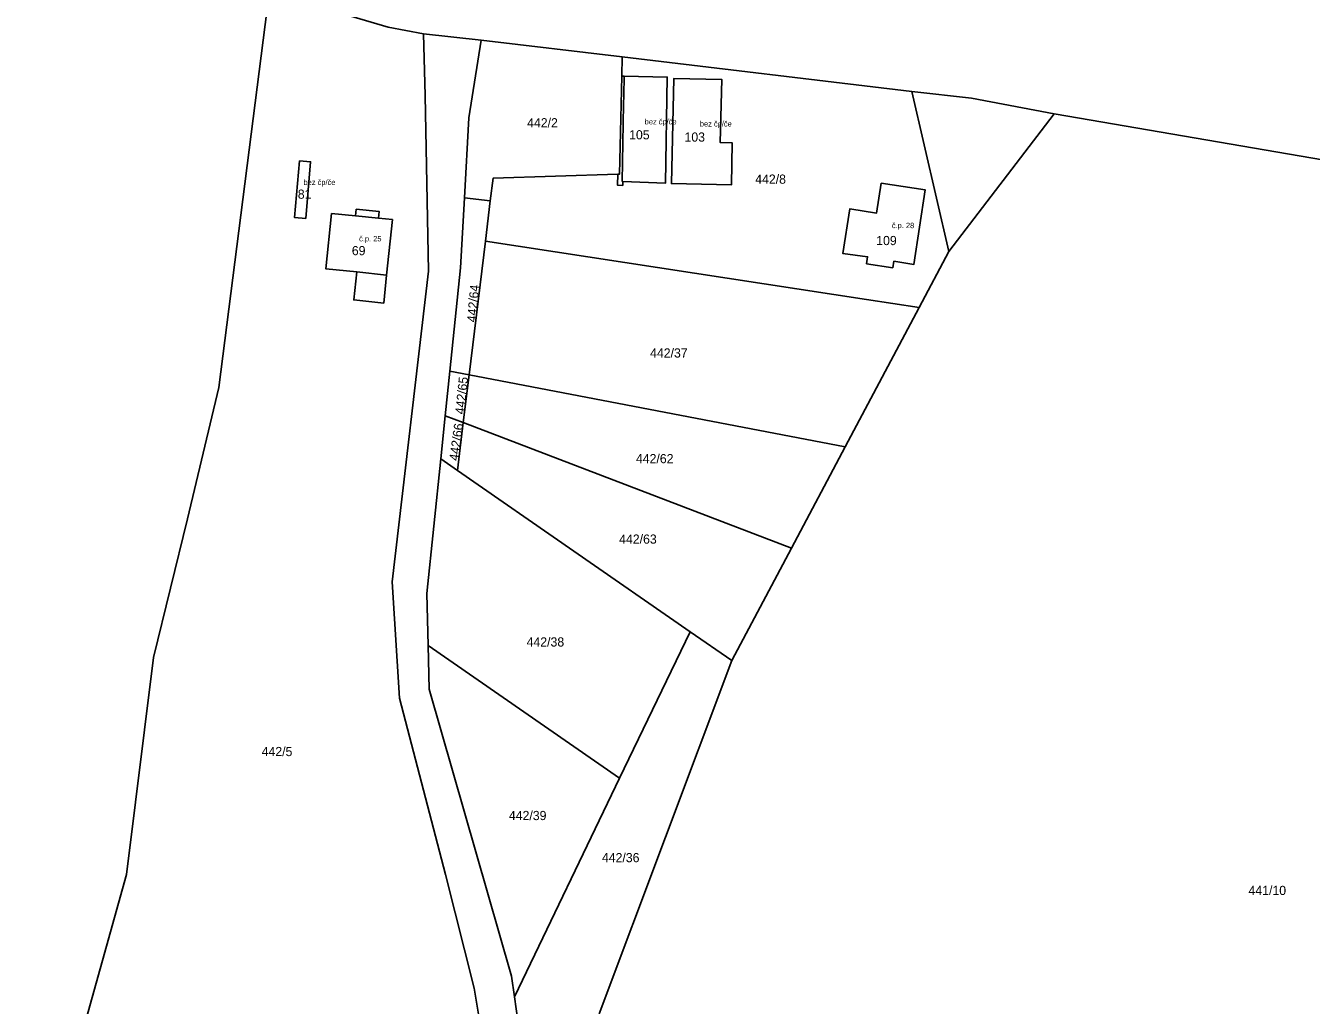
# Model space of a CAD drawing. Extents: x -880531 to -877616, y -1023932 to -1021350.
# Drawn here: x -880275.5 to -880037.5, y -1022775.2 to -1022593.9 of the extents above; entities that cross this region are included whole.
import ezdxf

# ---------------------------------------------------------------- set-up
doc = ezdxf.new("R2010")
doc.units = 0
for name, color, linetype in [('Definiční body', 7, 'Continuous'), ('Hranice parcel', 7, 'Continuous'), ('Parcelní čísla', 7, 'Continuous'), ('Polygon budovy', 7, 'Continuous'), ('Vnitřní kresba', 7, 'Continuous')]:
    doc.layers.add(name, color=color, linetype=linetype)

msp = doc.modelspace()

# ---------------------------------------------------------------- linework, layer by layer
at = {"layer": 'Hranice parcel'}
for p, q in [((-880191.14, -1022596.56), (-880201.85, -1022595.42)), ((-880165.02, -1022599.62), (-880191.14, -1022596.56)), ((-880165.11, -1022603.24), (-880165.02, -1022599.62)), ((-880165.11, -1022603.24), (-880164.68, -1022603.25)), ((-880194.24, -1022625.73), (-880189.45, -1022626.3)), ((-880189.45, -1022626.3), (-880190.36, -1022633.76)), ((-880190.36, -1022633.76), (-880193.39, -1022658.51)), ((-880123.76, -1022671.82), (-880110.08, -1022646.06)), ((-880196.94, -1022657.83), (-880197.79, -1022666.07)), ((-880193.39, -1022658.51), (-880196.94, -1022657.83)), ((-880193.39, -1022658.51), (-880194.47, -1022667.34)), ((-880193.39, -1022658.51), (-880123.76, -1022671.82)), ((-880198.62, -1022674.04), (-880197.79, -1022666.07)), ((-880197.79, -1022666.07), (-880194.47, -1022667.34)), ((-880194.47, -1022667.34), (-880195.55, -1022676.17)), ((-880194.47, -1022667.34), (-880133.71, -1022690.56)), ((-880133.71, -1022690.56), (-880123.76, -1022671.82)), ((-880195.55, -1022676.17), (-880198.62, -1022674.04)), ((-880152.45, -1022706.02), (-880195.55, -1022676.17)), ((-880133.71, -1022690.56), (-880144.75, -1022711.36)), ((-880152.45, -1022706.02), (-880165.51, -1022733.13)), ((-880144.75, -1022711.36), (-880152.45, -1022706.02)), ((-880200.98, -1022708.57), (-880165.51, -1022733.13)), ((-880169.29, -1022776.73), (-880144.75, -1022711.36)), ((-880165.51, -1022733.13), (-880184.98, -1022773.58))]:
    msp.add_line(p, q, dxfattribs=at)
for points in [[(-880201.85, -1022595.42), (-880208.37, -1022594.15), (-880224.11, -1022589.52), (-880229.6, -1022581.58)], [(-880275.46, -1022817.7), (-880256.82, -1022750.96), (-880251.78, -1022710.78), (-880245.5, -1022685.14), (-880239.72, -1022660.82), (-880229.65, -1022581.98)], [(-880201.85, -1022595.42), (-880201.5, -1022606.82), (-880200.91, -1022639.32), (-880207.63, -1022696.81), (-880206.25, -1022718.31), (-880197.77, -1022750.95), (-880192.42, -1022771.99), (-880190.9, -1022781.26)], [(-880191.14, -1022596.56), (-880193.43, -1022610.91), (-880194.24, -1022625.73)], [(-880085.09, -1022610.19), (-880100.38, -1022607.29), (-880111.43, -1022606.07), (-880165.02, -1022599.62)], [(-880165.85, -1022621.37), (-880165.55, -1022621.36), (-880165.11, -1022603.24)], [(-880164.68, -1022603.25), (-880156.7, -1022603.38), (-880157.02, -1022623.01), (-880164.89, -1022622.7)], [(-880146.89, -1022615.53), (-880146.62, -1022603.84), (-880155.47, -1022603.64), (-880155.91, -1022623.1), (-880144.81, -1022623.36), (-880144.66, -1022615.58), (-880146.89, -1022615.53)], [(-880110.08, -1022646.06), (-880104.57, -1022635.67), (-880085.09, -1022610.19)], [(-880085.09, -1022610.19), (-880006.95, -1022623.58), (-879948.33, -1022639.86), (-879895.51, -1022661.38), (-879854.76, -1022684.53)], [(-880223.61, -1022629.54), (-880222.73, -1022619.05), (-880224.76, -1022618.92), (-880225.68, -1022629.39), (-880223.61, -1022629.54)], [(-880189.45, -1022626.3), (-880188.93, -1022622.11), (-880165.85, -1022621.37)], [(-880164.89, -1022622.7), (-880164.92, -1022623.44), (-880165.89, -1022623.4), (-880165.85, -1022621.37)], [(-880117.08, -1022623.02), (-880117.95, -1022628.55), (-880122.9, -1022627.78), (-880124.2, -1022636.02), (-880119.61, -1022636.65), (-880119.79, -1022637.93), (-880114.95, -1022638.69), (-880114.75, -1022637.47), (-880111.03, -1022638.06), (-880108.92, -1022624.26), (-880117.08, -1022623.02)], [(-880196.94, -1022657.83), (-880194.95, -1022638.71), (-880194.24, -1022625.73)], [(-880218.86, -1022628.64), (-880219.91, -1022638.86), (-880214.19, -1022639.45), (-880214.73, -1022644.64), (-880209.18, -1022645.22), (-880208.64, -1022640.02), (-880207.57, -1022629.75), (-880210.12, -1022629.5), (-880210, -1022628.28), (-880214.26, -1022627.86), (-880214.38, -1022629.08), (-880218.86, -1022628.64)], [(-880110.08, -1022646.06), (-880119.83, -1022644.57), (-880190.36, -1022633.76)], [(-880200.98, -1022708.57), (-880201.21, -1022698.97), (-880198.62, -1022674.04)], [(-880184.98, -1022773.58), (-880185.52, -1022769.75), (-880200.78, -1022716.69), (-880200.98, -1022708.57)], [(-880183.96, -1022798.18), (-880184.04, -1022780.28), (-880184.98, -1022773.58)]]:
    msp.add_lwpolyline(points, dxfattribs=at)
at = {"layer": 'Polygon budovy'}
for points in [[(-880164.68, -1022603.25), (-880164.73, -1022606.78), (-880164.82, -1022608.39), (-880165.02, -1022622.7), (-880164.89, -1022622.7), (-880157.02, -1022623.01), (-880156.7, -1022603.38)], [(-880146.62, -1022603.84), (-880155.47, -1022603.64), (-880155.91, -1022623.1), (-880144.81, -1022623.36), (-880144.66, -1022615.58), (-880146.89, -1022615.53)], [(-880225.68, -1022629.39), (-880223.61, -1022629.54), (-880222.73, -1022619.05), (-880224.76, -1022618.92)], [(-880117.08, -1022623.02), (-880117.95, -1022628.55), (-880122.9, -1022627.78), (-880124.2, -1022636.02), (-880119.61, -1022636.65), (-880119.79, -1022637.93), (-880114.95, -1022638.69), (-880114.75, -1022637.47), (-880111.03, -1022638.06), (-880108.92, -1022624.26)], [(-880218.86, -1022628.64), (-880219.91, -1022638.86), (-880214.19, -1022639.45), (-880208.64, -1022640.02), (-880207.57, -1022629.75), (-880210.12, -1022629.5), (-880214.38, -1022629.08)]]:
    msp.add_lwpolyline(points, close=True, dxfattribs=at)
at = {"layer": 'Vnitřní kresba'}
for p, q in [((-880164.68, -1022603.25), (-880164.73, -1022606.78)), ((-880164.73, -1022606.78), (-880164.82, -1022608.39)), ((-880111.43, -1022606.07), (-880104.57, -1022635.67)), ((-880164.82, -1022608.39), (-880165.02, -1022622.7)), ((-880165.02, -1022622.7), (-880164.89, -1022622.7)), ((-880214.38, -1022629.08), (-880210.12, -1022629.5)), ((-880214.19, -1022639.45), (-880208.64, -1022640.02))]:
    msp.add_line(p, q, dxfattribs=at)

# ---------------------------------------------------------------- texts
at = {"layer": 'Definiční body'}
for s, p in [('bez čp/če', (-880160.88, -1022612.15)), ('bez čp/če', (-880150.66, -1022612.54)), ('bez čp/če', (-880224.03, -1022623.36)), ('č.p. 28', (-880115.12, -1022631.35)), ('č.p. 25', (-880213.74, -1022633.8))]:
    msp.add_text(s, height=1, dxfattribs=at).set_placement(p)
at = {"layer": 'Parcelní čísla'}
for s, p in [('442/2', (-880182.64, -1022612.7)), ('105', (-880163.758, -1022614.92)), ('103', (-880153.502, -1022615.34)), ('442/8', (-880140.41, -1022623.13)), ('81', (-880225.09, -1022625.91)), ('109', (-880118.01, -1022634.49)), ('69', (-880215.09, -1022636.36)), ('442/37', (-880159.871, -1022655.29)), ('442/62', (-880162.495, -1022674.85)), ('442/63', (-880165.601, -1022689.74)), ('442/38', (-880182.73, -1022708.77)), ('442/5', (-880231.78, -1022729.05)), ('442/39', (-880186.01, -1022740.89)), ('442/36', (-880168.79, -1022748.68)), ('441/10', (-880049.09, -1022754.75))]:
    msp.add_text(s, height=1.7, dxfattribs=at).set_placement(p)
for s, rotation, p in [('442/64', 85, (-880192.093, -1022648.825)), ('442/65', 84, (-880194.288, -1022665.868)), ('442/66', 82, (-880195.391, -1022674.484))]:
    msp.add_text(s, height=1.7, rotation=rotation, dxfattribs=at).set_placement(p)

doc.saveas('drawing.dxf')
